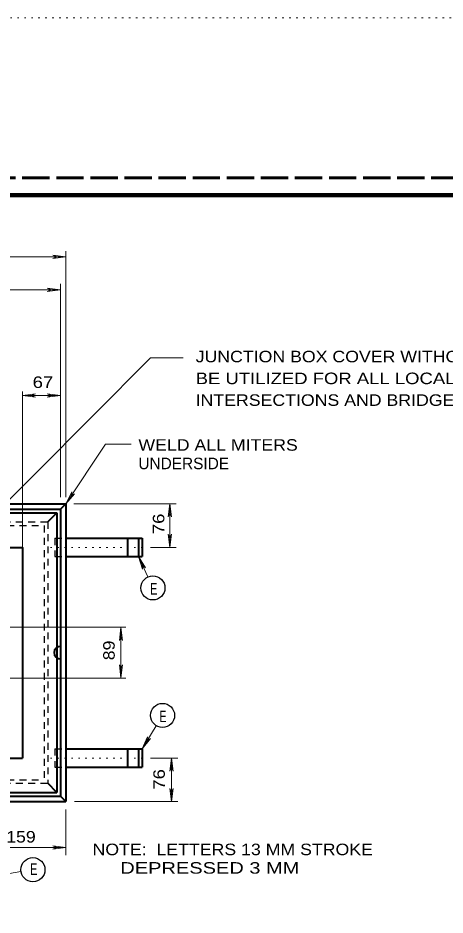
# Model space of a CAD drawing. Extents: x 312583 to 312854, y 144419 to 144597.
# Drawn here: x 312685.4 to 312713.6, y 144537.6 to 144596.8 of the extents above; entities that cross this region are included whole.
import ezdxf

# ---------------------------------------------------------------- set-up
doc = ezdxf.new("R2010")
doc.units = 0
doc.header["$LTSCALE"] = 0.3
for name, pattern in [('DOTTED', [1.5, 0.3, -1.2]), ('LONG_DASHED', [7.5, 6, -1.5]), ('SHORT_DASHED', [2.7, 1.5, -1.2])]:
    doc.linetypes.add(name, pattern=pattern)
doc.layers.add('1', color=7, linetype='Continuous', lineweight=13)
doc.layers.add('63', color=7, linetype='DOTTED', lineweight=13)

msp = doc.modelspace()

# ---------------------------------------------------------------- linework, layer by layer
at = {"layer": '1', "linetype": 'LONG_DASHED', "lineweight": 60}
msp.add_line((312851.75, 144586.2246), (312583.526, 144586.2246), dxfattribs=at)
at = {"layer": '1'}
for p, q in [((312688.5813, 144565.162), (312688.5813, 144581.3923)), ((312651.6816, 144581.0166), (312688.5813, 144581.0166)), ((312687.7149, 144581.124), (312687.9909, 144581.0166)), ((312688.5813, 144581.0166), (312687.7149, 144581.124)), ((312687.7149, 144580.9093), (312687.9909, 144581.0166)), ((312688.5813, 144581.0166), (312687.7149, 144580.9093)), ((312687.3546, 144578.9543), (312687.6306, 144578.847)), ((312688.2209, 144578.847), (312687.3546, 144578.9543)), ((312688.2209, 144565.162), (312688.2209, 144579.2456)), ((312652.0419, 144578.847), (312688.2209, 144578.847)), ((312687.3546, 144578.7396), (312687.6306, 144578.847)), ((312688.2209, 144578.847), (312687.3546, 144578.7396)), ((312685.7063, 144561.85), (312685.7063, 144572.131)), ((312685.7063, 144571.8626), (312686.5726, 144571.97)), ((312685.7063, 144571.8626), (312688.2209, 144571.8626)), ((312685.7063, 144571.8626), (312686.5726, 144571.7553)), ((312686.5726, 144571.97), (312686.2966, 144571.8626)), ((312686.5726, 144571.7553), (312686.2966, 144571.8626)), ((312687.3546, 144571.97), (312687.6306, 144571.8626)), ((312688.2209, 144571.8626), (312687.3546, 144571.97)), ((312687.3546, 144571.7553), (312687.6306, 144571.8626)), ((312688.2209, 144571.8626), (312687.3546, 144571.7553)), ((312691.1956, 144568.6503), (312688.5813, 144564.725)), ((312692.8899, 144568.6503), (312691.1956, 144568.6503)), ((312688.5813, 144564.725), (312688.9723, 144565.507)), ((312688.5813, 144564.725), (312689.1486, 144565.3843)), ((312688.9723, 144565.507), (312688.9109, 144565.2156)), ((312689.1486, 144565.3843), (312688.9109, 144565.2156)), ((312689.0949, 144564.725), (312695.8646, 144564.725)), ((312695.4429, 144564.725), (312695.3356, 144563.8586)), ((312695.4429, 144561.85), (312695.4429, 144564.725)), ((312695.4429, 144564.725), (312695.5503, 144563.8586)), ((312695.3356, 144563.8586), (312695.4429, 144564.1346)), ((312695.5503, 144563.8586), (312695.4429, 144564.1346)), ((312695.3356, 144562.7163), (312695.4429, 144562.4403)), ((312695.4429, 144561.85), (312695.3356, 144562.7163)), ((312695.5503, 144562.7163), (312695.4429, 144562.4403)), ((312695.4429, 144561.85), (312695.5503, 144562.7163)), ((312694.1703, 144561.85), (312695.8646, 144561.85)), ((312693.9939, 144559.895), (312693.3729, 144561.252)), ((312693.3729, 144561.252), (312693.6336, 144560.4163)), ((312693.3729, 144561.252), (312693.8329, 144560.5083)), ((312693.6336, 144560.4163), (312693.6183, 144560.7153)), ((312693.8329, 144560.5083), (312693.6183, 144560.7153)), ((312683.3066, 144556.5753), (312692.5296, 144556.5753)), ((312692.2153, 144556.5753), (312692.1079, 144555.709)), ((312692.2153, 144553.225), (312692.2153, 144556.5753)), ((312692.2153, 144556.5753), (312692.3226, 144555.709)), ((312692.1079, 144555.709), (312692.2153, 144555.985)), ((312692.3226, 144555.709), (312692.2153, 144555.985)), ((312692.1079, 144554.0913), (312692.2153, 144553.8153)), ((312692.2153, 144553.225), (312692.1079, 144554.0913)), ((312692.3226, 144554.0913), (312692.2153, 144553.8153)), ((312692.2153, 144553.225), (312692.3226, 144554.0913)), ((312683.3066, 144553.225), (312692.5296, 144553.225)), ((312694.5459, 144550.0816), (312693.6106, 144548.556)), ((312693.6106, 144548.556), (312693.9709, 144549.3456)), ((312693.9709, 144549.3456), (312693.9173, 144549.0543)), ((312693.6106, 144548.556), (312694.1549, 144549.2383)), ((312694.1549, 144549.2383), (312693.9173, 144549.0543)), ((312694.1703, 144547.9503), (312695.9719, 144547.9503)), ((312695.5503, 144547.9503), (312695.4429, 144547.084)), ((312695.5503, 144545.0753), (312695.5503, 144547.9503)), ((312695.5503, 144547.9503), (312695.6576, 144547.084)), ((312695.4429, 144547.084), (312695.5503, 144547.36)), ((312695.6576, 144547.084), (312695.5503, 144547.36)), ((312695.4429, 144545.9416), (312695.5503, 144545.6656)), ((312695.5503, 144545.0753), (312695.4429, 144545.9416)), ((312695.6576, 144545.9416), (312695.5503, 144545.6656)), ((312695.5503, 144545.0753), (312695.6576, 144545.9416)), ((312688.5813, 144544.5616), (312688.5813, 144541.5486)), ((312689.1486, 144545.0753), (312695.9719, 144545.0753)), ((312688.5813, 144542.0393), (312682.5936, 144542.0393)), ((312687.7149, 144542.1466), (312687.9909, 144542.0393)), ((312688.5813, 144542.0393), (312687.7149, 144542.1466)), ((312687.7149, 144541.932), (312687.9909, 144542.0393)), ((312688.5813, 144542.0393), (312687.7149, 144541.932)), ((312685.6143, 144540.4523), (312683.1916, 144540.046))]:
    msp.add_line(p, q, dxfattribs=at)
at = {"layer": '1', "lineweight": 40}
for p, q in [((312651.6816, 144564.725), (312688.5813, 144564.725)), ((312688.2209, 144564.3646), (312688.5813, 144564.725)), ((312688.5813, 144564.725), (312688.5813, 144545.0753)), ((312652.0419, 144564.3646), (312688.2209, 144564.3646)), ((312652.2796, 144564.127), (312687.9833, 144564.127)), ((312687.3853, 144563.529), (312687.9833, 144564.127)), ((312687.9833, 144564.127), (312687.9833, 144545.681)), ((312688.2209, 144564.3646), (312688.2209, 144545.4356)), ((312688.5813, 144562.448), (312693.6106, 144562.448)), ((312692.6523, 144562.448), (312692.6523, 144561.252)), ((312693.3729, 144562.448), (312693.3729, 144561.252)), ((312693.6106, 144562.448), (312693.6106, 144561.252)), ((312688.5813, 144561.252), (312693.6106, 144561.252)), ((312688.5813, 144548.556), (312693.6106, 144548.556)), ((312692.6523, 144548.556), (312692.6523, 144547.3523)), ((312693.3729, 144548.556), (312693.3729, 144547.3523)), ((312693.6106, 144548.556), (312693.6106, 144547.3523)), ((312654.5566, 144547.9503), (312685.7063, 144547.9503)), ((312688.5813, 144547.3523), (312693.6106, 144547.3523)), ((312687.9833, 144545.681), (312687.3853, 144546.279)), ((312652.0419, 144545.4356), (312688.2209, 144545.4356)), ((312652.2796, 144545.681), (312687.9833, 144545.681)), ((312688.5813, 144545.0753), (312688.2209, 144545.4356)), ((312651.6816, 144545.0753), (312688.5813, 144545.0753))]:
    msp.add_line(p, q, dxfattribs=at)
at = {"layer": '1', "linetype": 'SHORT_DASHED', "lineweight": 25}
for p, q in [((312652.8853, 144563.529), (312687.3853, 144563.529)), ((312687.3853, 144563.529), (312687.3853, 144546.279)), ((312653.1229, 144563.2836), (312687.1399, 144563.2836)), ((312687.1399, 144563.2836), (312687.1399, 144546.5166)), ((312687.8606, 144562.448), (312687.8606, 144561.252)), ((312687.8606, 144562.448), (312688.5813, 144562.448)), ((312687.8606, 144561.252), (312688.5813, 144561.252)), ((312687.8606, 144548.556), (312687.8606, 144547.3523)), ((312687.8606, 144548.556), (312688.5813, 144548.556)), ((312687.8606, 144547.3523), (312688.5813, 144547.3523)), ((312652.8853, 144546.279), (312687.3853, 144546.279))]:
    msp.add_line(p, q, dxfattribs=at)
at = {"layer": '1', "linetype": 'DOTTED'}
for p, q in [((312687.5616, 144561.85), (312693.9633, 144561.85)), ((312687.5616, 144547.9503), (312693.9633, 144547.9503))]:
    msp.add_line(p, q, dxfattribs=at)
at = {"layer": '1', "lineweight": 158}
msp.add_lwpolyline([(312616.5, 144423.1446), (312616.5, 144585.0846), (312849, 144585.0846)], dxfattribs=at)
at = {"layer": '1'}
msp.add_lwpolyline([(312675.1109, 144555.226), (312694.1626, 144574.3466), (312696.3246, 144574.3466)], dxfattribs=at)
at = {"layer": '1', "linetype": 'SHORT_DASHED', "lineweight": 25}
msp.add_lwpolyline([(312653.1229, 144563.2836), (312653.1229, 144546.5166), (312687.1399, 144546.5166)], dxfattribs=at)
at = {"layer": '1', "lineweight": 40}
msp.add_lwpolyline([(312654.5566, 144561.85), (312685.7063, 144561.85), (312685.7063, 144547.9503)], dxfattribs=at)
at = {"layer": '1', "lineweight": 25}
for centre in [(312694.3226, 144559.1743), (312694.959, 144550.7601), (312686.403, 144540.5788)]:
    msp.add_circle(centre, 0.7964, dxfattribs=at)
at = {"layer": '1', "lineweight": 40}
msp.add_arc((312688.22, 144554.9021), 0.414, 90, 270, dxfattribs=at)
at = {"layer": '63'}
msp.add_line((312601.2, 144596.7846), (312853.5, 144596.7846), dxfattribs=at)

# ---------------------------------------------------------------- texts
at = {"layer": '1'}
for s, width, p in [('JUNCTION BOX COVER WITHOUT D.O.T. LOGO SHALL', 1.15, (312697.1449, 144574.062)), ('67 ', 1.2, (312686.3857, 144572.3666)), ('BE UTILIZED FOR ALL LOCAL SIGNALIZED', 1.2, (312697.1449, 144572.6206)), ('INTERSECTIONS AND BRIDGES ON LOCAL ROADS.', 1.15, (312697.1449, 144571.187)), ('WELD ALL MITERS', 1.15, (312693.3653, 144568.2276)), ('E', 0.7, (312694.1453, 144558.7335)), ('E', 0.7, (312694.7462, 144550.3155)), ('159 ', 1.15, (312684.6397, 144542.3709)), ('NOTE:  LETTERS 13 MM STROKE', 1.15, (312690.3372, 144541.5381)), ('E', 0.7, (312686.2256, 144540.2406)), ('     DEPRESSED 3 MM', 1.3, (312690.3372, 144540.3181))]:
    msp.add_text(s, height=0.76, dxfattribs=dict(at, width=width)).set_placement(p)
msp.add_text('UNDERSIDE', height=0.76, dxfattribs=at).set_placement((312693.3653, 144567.0076))
for s, width, p in [('76 ', 1.2, (312695.078, 144562.7213)), ('89 ', 1.15, (312691.8018, 144554.4002)), ('76 ', 1.2, (312695.1118, 144545.8629))]:
    msp.add_text(s, height=0.76, rotation=90, dxfattribs=dict(at, width=width)).set_placement(p)

doc.saveas('drawing.dxf')
